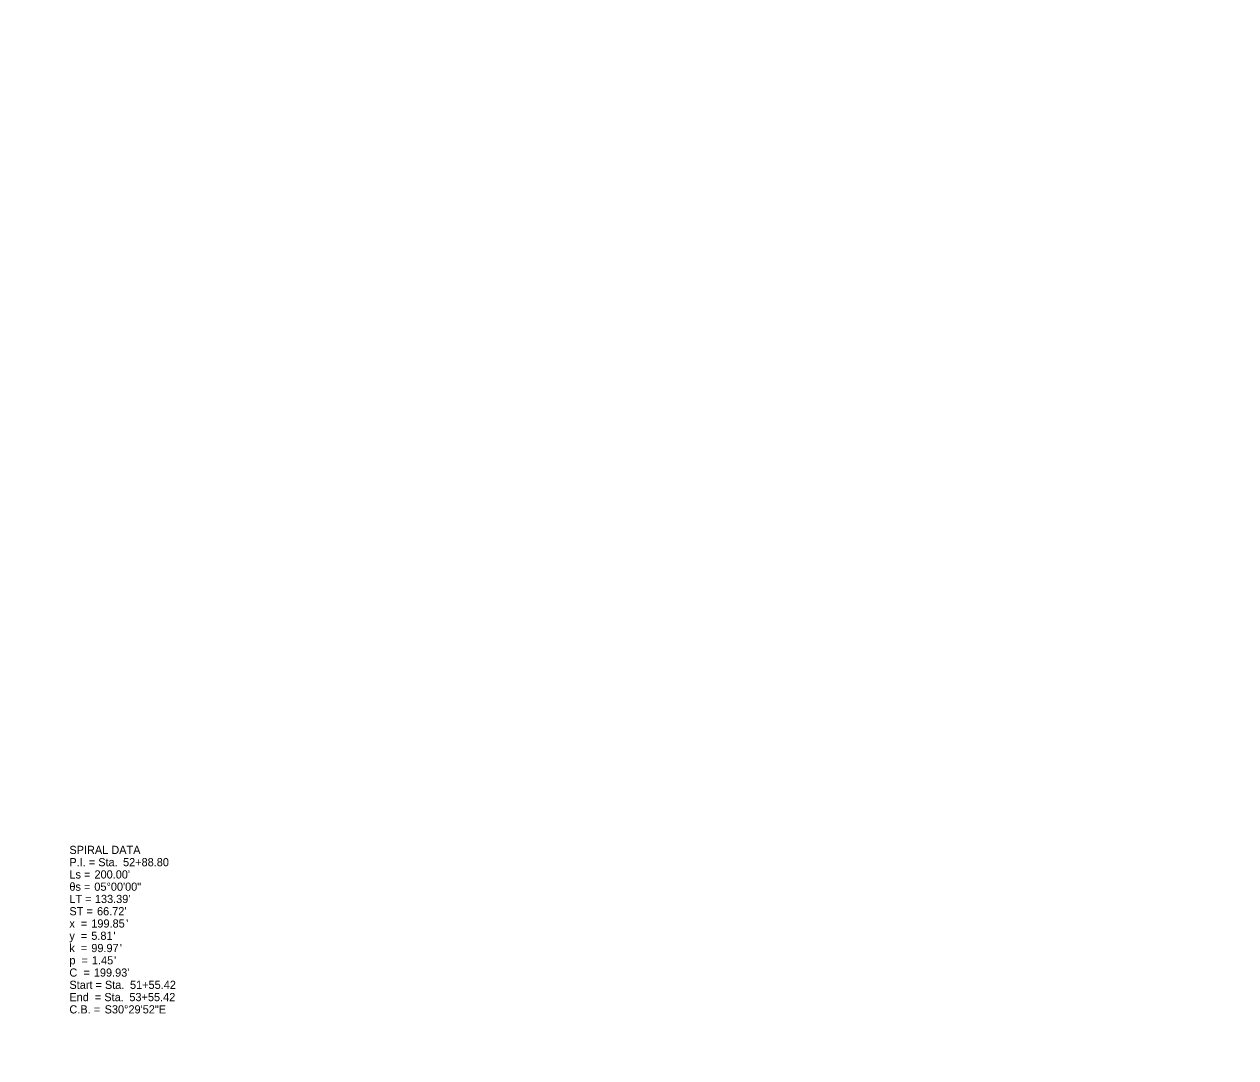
# Model space of a CAD drawing. Extents: x 1492452 to 1496782, y 514026 to 517659.
# Drawn here: x 1494477.9 to 1494892.9, y 515125.3 to 515479.1 of the extents above; entities that cross this region are included whole.
import ezdxf

# ---------------------------------------------------------------- set-up
doc = ezdxf.new("R2010")
doc.units = 0
for name, color, linetype in [('BR_X_SV_Abut', 7, 'Continuous'), ('Default', 7, 'Continuous'), ('DT_X_Triangles', 7, 'Continuous'), ('GE_X_Cells', 7, 'Continuous'), ('PV_X_COP', 7, 'Continuous')]:
    doc.layers.add(name, color=color, linetype=linetype)

msp = doc.modelspace()

# ---------------------------------------------------------------- linework, layer by layer
at = {"layer": 'Default'}
msp.add_arc((1486425.91, 524780.42), 12277.67, 302.444021, 313.600151, dxfattribs=at)
at = {"layer": 'GE_X_Cells'}
msp.add_arc((1486425.91, 524780.42), 12277.67, 302.444021, 313.600151, dxfattribs=at)

# ---------------------------------------------------------------- texts
at = {"layer": 'BR_X_SV_Abut'}
for s, p in [('SPIRAL DATA', (1494493.34, 515195.03)), ('P.I. = Sta. ', (1494493.34, 515190.83)), ('52+88.80', (1494511.71, 515190.83)), ('Ls = ', (1494493.34, 515186.63)), ("200.00'", (1494501.93, 515186.63)), ('θs = ', (1494493.34, 515182.43)), ('05°00\'00"', (1494501.88, 515182.43)), ('LT = ', (1494493.34, 515178.23)), ("133.39'", (1494502.07, 515178.23)), ('ST = ', (1494493.34, 515174.03)), ("66.72'", (1494502.8, 515174.03)), ('x  = ', (1494493.34, 515169.83)), ('199.85', (1494500.84, 515169.83)), ("'", (1494512.8, 515169.83)), ('y  = ', (1494493.34, 515165.63)), ('5.81', (1494500.84, 515165.63)), ("'", (1494508.45, 515165.63)), ('k  = ', (1494493.34, 515161.43)), ('99.97', (1494500.84, 515161.43)), ("'", (1494510.63, 515161.43)), ('p  = ', (1494493.34, 515157.23)), ('1.45', (1494501.06, 515157.23)), ("'", (1494508.67, 515157.23)), ('C  = ', (1494493.34, 515153.03)), ("199.93'", (1494501.71, 515153.03)), ('Start = Sta. ', (1494493.34, 515148.83)), ('51+55.42', (1494514.1, 515148.83)), ('End  = Sta. ', (1494493.34, 515144.63)), ('53+55.42', (1494513.89, 515144.63)), ('C.B. = ', (1494493.34, 515140.43)), ('S30°29\'52"E', (1494505.41, 515140.43))]:
    msp.add_text(s, height=2.8, dxfattribs=at).set_placement(p)
at = {"layer": 'DT_X_Triangles'}
for s, p in [('SPIRAL DATA', (1494493.34, 515195.03)), ('P.I. = Sta. ', (1494493.34, 515190.83)), ('52+88.80', (1494511.71, 515190.83)), ('Ls = ', (1494493.34, 515186.63)), ("200.00'", (1494501.93, 515186.63)), ('θs = ', (1494493.34, 515182.43)), ('05°00\'00"', (1494501.88, 515182.43)), ('LT = ', (1494493.34, 515178.23)), ("133.39'", (1494502.07, 515178.23)), ('ST = ', (1494493.34, 515174.03)), ("66.72'", (1494502.8, 515174.03)), ('x  = ', (1494493.34, 515169.83)), ('199.85', (1494500.84, 515169.83)), ("'", (1494512.8, 515169.83)), ('y  = ', (1494493.34, 515165.63)), ('5.81', (1494500.84, 515165.63)), ("'", (1494508.45, 515165.63)), ('k  = ', (1494493.34, 515161.43)), ('99.97', (1494500.84, 515161.43)), ("'", (1494510.63, 515161.43)), ('p  = ', (1494493.34, 515157.23)), ('1.45', (1494501.06, 515157.23)), ("'", (1494508.67, 515157.23)), ('C  = ', (1494493.34, 515153.03)), ("199.93'", (1494501.71, 515153.03)), ('Start = Sta. ', (1494493.34, 515148.83)), ('51+55.42', (1494514.1, 515148.83)), ('End  = Sta. ', (1494493.34, 515144.63)), ('53+55.42', (1494513.89, 515144.63)), ('C.B. = ', (1494493.34, 515140.43)), ('S30°29\'52"E', (1494505.41, 515140.43))]:
    msp.add_text(s, height=2.8, dxfattribs=at).set_placement(p)
at = {"layer": 'PV_X_COP'}
for s, p in [('SPIRAL DATA', (1494493.34, 515195.03)), ('P.I. = Sta. ', (1494493.34, 515190.83)), ('52+88.80', (1494511.71, 515190.83)), ('Ls = ', (1494493.34, 515186.63)), ("200.00'", (1494501.93, 515186.63)), ('θs = ', (1494493.34, 515182.43)), ('05°00\'00"', (1494501.88, 515182.43)), ('LT = ', (1494493.34, 515178.23)), ("133.39'", (1494502.07, 515178.23)), ('ST = ', (1494493.34, 515174.03)), ("66.72'", (1494502.8, 515174.03)), ('x  = ', (1494493.34, 515169.83)), ('199.85', (1494500.84, 515169.83)), ("'", (1494512.8, 515169.83)), ('y  = ', (1494493.34, 515165.63)), ('5.81', (1494500.84, 515165.63)), ("'", (1494508.45, 515165.63)), ('k  = ', (1494493.34, 515161.43)), ('99.97', (1494500.84, 515161.43)), ("'", (1494510.63, 515161.43)), ('p  = ', (1494493.34, 515157.23)), ('1.45', (1494501.06, 515157.23)), ("'", (1494508.67, 515157.23)), ('C  = ', (1494493.34, 515153.03)), ("199.93'", (1494501.71, 515153.03)), ('Start = Sta. ', (1494493.34, 515148.83)), ('51+55.42', (1494514.1, 515148.83)), ('End  = Sta. ', (1494493.34, 515144.63)), ('53+55.42', (1494513.89, 515144.63)), ('C.B. = ', (1494493.34, 515140.43)), ('S30°29\'52"E', (1494505.41, 515140.43))]:
    msp.add_text(s, height=2.8, dxfattribs=at).set_placement(p)

doc.saveas('drawing.dxf')
